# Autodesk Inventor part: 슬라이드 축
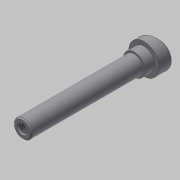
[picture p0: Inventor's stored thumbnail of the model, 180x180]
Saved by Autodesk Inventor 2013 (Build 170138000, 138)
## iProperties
Created: 2015-11
Part Number: 슬라이드 축
Document SubType Name: 모델링
Designer: mdu
Mass: 174.302 g
Surface Area: 67.5858 cm^2
Volume: 21.572 cm^3
Density: 8.08 g/cm^3
Material: 스테인리스강
변환 표준: STEP AP214IS
파일 이름: C:\Users\SeoGD\Desktop\?쒗뿕\異?stp
전처리기: Build: 253, Release: 2010 SP1 - Date: Wed 07/29/2009
전송 단위: 밀리미터
불확실성: 0.01
Author: mdu
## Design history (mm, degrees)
sketch "스케치1"
  geometry: L1 (0, 100)-(7.5, 100); L2 (7.5, 100)-(7.5, 0); L3 (7.5, 0)-(12.5, 0); L4 (12.5, 0)-(12.5, -17); L5 (12.5, -17)-(0, -17); L6 (0, -17)-(0, 100); 1 further point
  constraints: 12 end point, 2 parallel, 2 point on line, 1 perpendicular, 1 vertical
  dimensions: "d0" = 100 distance from line of L1 point (0, 0); "d1" = 15 diameter of L2 L6; "d2" = 25 diameter of L4 L6; "d3" = 17 distance of L3.end L4.end
revolve "회전1" sketch "스케치1" stored, may be unused: angle "d4" = 90 deg
sketch "스케치2"
  geometry: L1 (12.5, 0)-(12.5, -17) reference; L2 (-12.5, -17)-(12.5, -17) reference; L3 (-12.5, 0)-(-12.5, -17) reference; L4 (12.5, -5)-(-12.5, -11.699); L5 (-12.5, 0)-(12.5, 0) reference; 1 further point
  constraints: 2 end point, 2 point on line
  dimensions: "d5" = 75 deg angle of L1 L4; "d6" = 5 distance from line of L4.start L5
extrude "돌출1" cut sketch "스케치2" stored distance "d7" = 10; taper "d8" = 0 deg
chamfer "모따기1" distance "d9" = 1; stored, may be unused: second distance "d10" = 2, angle "d11" = 45 deg
fillet "모깎기1" dims "d12" = 0.5
hole "구멍1" diameter "d15" = 6.647; stored, may be unused: countersink angle "d19" = 90 deg, drill point angle "d21" = 118 deg; dims "d13" = 10, "d14" = 10, "d16" = 17, "d17" = 4, "d18" = 2, "d20" = 20
chamfer "모따기2" distance "d22" = 1; stored, may be unused: second distance "d23" = 2, angle "d24" = 45 deg
sketch "스케치3"
  geometry: C1 r 9 at (0, 0); 1 further point
  constraints: 1 centre point, 1 coincident
  dimensions: "d25" = 18 diameter of C1
extrude "돌출2" join sketch "스케치3" distance "d26" = 8; taper "d27" = 0 deg
node "솔리드1"
node "솔리드 본체"
node "곡면 본체"
node "솔리드2"
